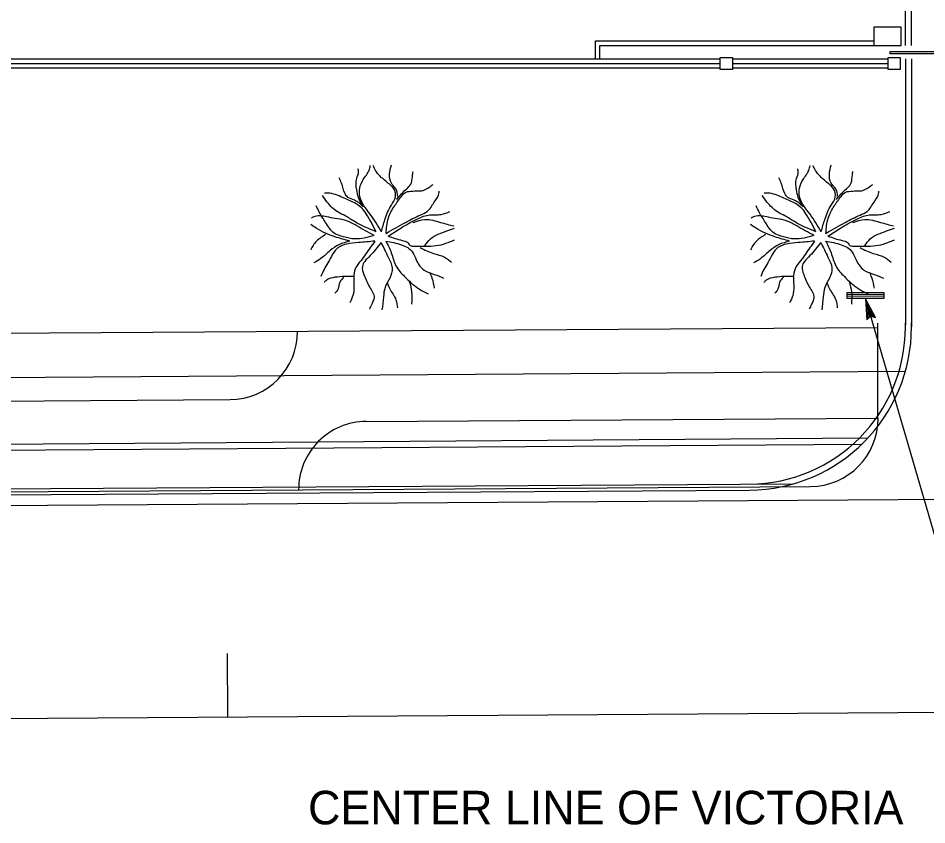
# Model space of a CAD drawing. Extents: x 6711323 to 6714641, y 1869258 to 1871224.
# Drawn here: x 6713028.7 to 6713129, y 1869579.7 to 1869668.7 of the extents above; entities that cross this region are included whole.
import ezdxf

# ---------------------------------------------------------------- set-up
doc = ezdxf.new("R2010")
doc.units = 0
for name, color, linetype in [('49 Planting', 7, 'Continuous'), ('Curb Gutter (21)', 7, 'Continuous'), ('Level 11', 7, 'Continuous'), ('Level 13', 7, 'Continuous'), ('Level 14', 7, 'Continuous'), ('Level 21', 7, 'Continuous'), ('Level 46', 7, 'Continuous'), ('Misc CnstDet(22)', 7, 'Continuous'), ('Profile Grid (9)', 7, 'Continuous'), ('Undefined (Lv26)', 7, 'Continuous')]:
    doc.layers.add(name, color=color, linetype=linetype)

msp = doc.modelspace()

# ---------------------------------------------------------------- linework, layer by layer
at = {"layer": '49 Planting'}
for p, q in [((6713124.24, 1869638.26), (6713120.2, 1869638.23)), ((6713124.25, 1869638.06), (6713120.2, 1869638.04)), ((6713122.22, 1869637.78), (6713130.69, 1869608.81)), ((6713122.22, 1869637.78), (6713122.22, 1869637.78)), ((6713122.37, 1869635.45), (6713122.37, 1869635.45)), ((6713123.35, 1869635.73), (6713123.35, 1869635.73))]:
    msp.add_line(p, q, dxfattribs=at)
for points in [[(6713120.22, 1869638.49), (6713124.25, 1869638.49), (6713124.25, 1869637.83), (6713120.22, 1869637.83)], [(6713123.35, 1869635.73), (6713122.22, 1869637.78), (6713122.37, 1869635.45), (6713122.48, 1869635.56), (6713122.37, 1869637.27), (6713123.2, 1869635.77), (6713123.05, 1869635.81), (6713122.51, 1869636.77), (6713122.59, 1869635.68), (6713122.69, 1869635.79), (6713122.66, 1869636.27), (6713122.89, 1869635.85), (6713122.78, 1869635.88), (6713122.37, 1869635.45), (6713122.78, 1869635.88)]]:
    msp.add_lwpolyline(points, close=True, dxfattribs=at)
at = {"layer": 'Curb Gutter (21)'}
for p, q in [((6713126.65, 1869665.74), (6713126.65, 1869718.07)), ((6713127.31, 1869665.74), (6713127.31, 1869718.07)), ((6713126.65, 1869664.24), (6713126.65, 1869634.91)), ((6713127.31, 1869664.24), (6713127.31, 1869634.67))]:
    msp.add_line(p, q, dxfattribs=at)
at = {"layer": 'Level 11'}
for p, q in [((6712930.92, 1869633.37), (6713123.56, 1869634.62)), ((6713001.11, 1869626.33), (6713052.11, 1869626.66)), ((6713067.13, 1869624.25), (6713123.56, 1869624.62)), ((6712940.02, 1869615.93), (6713116.17, 1869617.07)), ((6712948.69, 1869614.49), (6713181.17, 1869615.99))]:
    msp.add_line(p, q, dxfattribs=at)
for centre, start, end in [((6713052.06, 1869634.16), 270.3699, 0.3699), ((6713067.18, 1869616.75), 90.3699, 180.3699), ((6713116.12, 1869624.57), 270.3699, 0.3699)]:
    msp.add_arc(centre, 7.5, start, end, dxfattribs=at)
at = {"layer": 'Level 13'}
msp.add_line((6712709.06, 1869589.44), (6713820.2, 1869596.61), dxfattribs=at)
for centre, start, end in [((6713052.06, 1869634.16), 270.3699, 0.3699), ((6713067.18, 1869616.75), 90.3699, 180.3699)]:
    msp.add_arc(centre, 7.5, start, end, dxfattribs=at)
at = {"layer": 'Level 14'}
msp.add_lwpolyline([(6713051.79, 1869598.65), (6713051.83, 1869591.65)], dxfattribs=at)
at = {"layer": 'Level 21'}
for p, q in [((6713123.56, 1869635.1), (6713123.56, 1869624.62)), ((6712929.57, 1869633.37), (6713123.56, 1869634.62)), ((6713001.11, 1869626.33), (6713052.11, 1869626.66)), ((6713067.13, 1869624.25), (6713123.56, 1869624.62)), ((6712940.02, 1869615.93), (6713116.17, 1869617.07)), ((6712948.69, 1869614.49), (6713181.17, 1869615.99)), ((6712948.69, 1869614.49), (6713181.17, 1869615.99))]:
    msp.add_line(p, q, dxfattribs=at)
msp.add_arc((6713116.12, 1869624.57), 7.5, 270.3699, 0.3699, dxfattribs=at)
at = {"layer": 'Level 46'}
for p, q in [((6713126.65, 1869634.67), (6713126.65, 1869635.12)), ((6713127.31, 1869634.67), (6713127.31, 1869635.13)), ((6712931.76, 1869628.4), (6713126.64, 1869629.8)), ((6712936.07, 1869621.1), (6713122.51, 1869622.44)), ((6712936.75, 1869620.44), (6713121.86, 1869621.76)), ((6712944.24, 1869616.29), (6713114.28, 1869617.37)), ((6712949.09, 1869615.65), (6713109.43, 1869616.67))]:
    msp.add_line(p, q, dxfattribs=at)
for radius in [17.33, 18]:
    msp.add_arc((6713109.31, 1869634.67), radius, 270.3648, 0, dxfattribs=at)
at = {"layer": 'Misc CnstDet(22)'}
for p, q in [((6713123.15, 1869667.74), (6713123.15, 1869665.74)), ((6713126.15, 1869667.74), (6713123.15, 1869667.74)), ((6713126.15, 1869665.74), (6713126.15, 1869667.74)), ((6713092.42, 1869666.24), (6713123.17, 1869666.24)), ((6713092.42, 1869664.24), (6713092.42, 1869666.24)), ((6713092.92, 1869665.74), (6713126.14, 1869665.74)), ((6713092.92, 1869664.24), (6713092.92, 1869665.74)), ((6713123.15, 1869665.74), (6713126.15, 1869665.74)), ((6712985.7, 1869663.74), (6713106.2, 1869663.74)), ((6713107.54, 1869663.74), (6713124.67, 1869663.74))]:
    msp.add_line(p, q, dxfattribs=at)
msp.add_lwpolyline([(6713124.96, 1869665.07), (6713158.81, 1869665.07), (6713158.81, 1869664.82), (6713124.96, 1869664.82)], close=True, dxfattribs=at)
msp.add_lwpolyline([(6713124.96, 1869665.07), (6713158.81, 1869665.07), (6713158.81, 1869664.82), (6713124.96, 1869664.82)], close=True, dxfattribs=at)
at = {"layer": 'Profile Grid (9)'}
for points in [[(6713066.8, 1869647.94), (6713066.29, 1869648.96), (6713066.09, 1869649.8), (6713066.09, 1869651.05), (6713066.29, 1869651.77), (6713066.22, 1869652.13)], [(6713068.81, 1869645.18), (6713067.58, 1869647.1), (6713066.42, 1869649.08), (6713066.42, 1869649.98), (6713066.8, 1869650.93), (6713067.45, 1869651.95), (6713067.58, 1869652.49)], [(6713068.81, 1869645.18), (6713069.2, 1869646.5), (6713069.91, 1869648.12), (6713070.37, 1869649.02), (6713070.17, 1869649.92), (6713069.66, 1869650.45), (6713068.68, 1869651.29), (6713068.16, 1869651.95), (6713067.91, 1869652.49)], [(6713070.63, 1869649.08), (6713070.43, 1869649.86), (6713070.3, 1869650.04), (6713069.91, 1869650.52), (6713069.72, 1869651.53), (6713069.91, 1869652.55)], [(6713115.34, 1869647.94), (6713114.82, 1869648.96), (6713114.62, 1869649.8), (6713114.62, 1869651.05), (6713114.82, 1869651.77), (6713114.75, 1869652.13)], [(6713117.35, 1869645.18), (6713116.11, 1869647.1), (6713114.95, 1869649.08), (6713114.95, 1869649.98), (6713115.34, 1869650.93), (6713115.98, 1869651.95), (6713116.11, 1869652.49)], [(6713117.35, 1869645.18), (6713117.73, 1869646.5), (6713118.45, 1869648.12), (6713118.9, 1869649.02), (6713118.71, 1869649.92), (6713118.19, 1869650.45), (6713117.22, 1869651.29), (6713116.7, 1869651.95), (6713116.44, 1869652.49)], [(6713119.16, 1869649.08), (6713118.97, 1869649.86), (6713118.84, 1869650.04), (6713118.45, 1869650.52), (6713118.25, 1869651.53), (6713118.45, 1869652.55)], [(6713066.8, 1869647.94), (6713065.83, 1869648.66), (6713065.12, 1869648.96), (6713064.8, 1869649.38), (6713064.41, 1869650.52), (6713064.15, 1869651.11)], [(6713070.5, 1869648.72), (6713071.21, 1869649.56), (6713072.12, 1869650.57), (6713072.25, 1869651.47), (6713072.31, 1869651.83)], [(6713115.34, 1869647.94), (6713114.36, 1869648.66), (6713113.65, 1869648.96), (6713113.33, 1869649.38), (6713112.94, 1869650.52), (6713112.68, 1869651.11)], [(6713119.03, 1869648.72), (6713119.74, 1869649.56), (6713120.65, 1869650.57), (6713120.78, 1869651.47), (6713120.84, 1869651.83)], [(6713069.33, 1869645), (6713069.59, 1869646.68), (6713070.24, 1869648), (6713071.02, 1869649.08), (6713071.53, 1869649.56), (6713071.86, 1869649.62), (6713072.7, 1869649.68), (6713073.41, 1869649.74), (6713074.26, 1869650.22), (6713074.51, 1869650.4)], [(6713117.86, 1869645), (6713118.12, 1869646.68), (6713118.77, 1869648), (6713119.55, 1869649.08), (6713120.07, 1869649.56), (6713120.39, 1869649.62), (6713121.23, 1869649.68), (6713121.95, 1869649.74), (6713122.79, 1869650.22), (6713123.05, 1869650.4)], [(6713068.23, 1869645.18), (6713065.85, 1869646.29), (6713064.81, 1869646.93), (6713064.03, 1869647.33), (6713062.83, 1869648.45), (6713062.31, 1869649.17)], [(6713068.23, 1869645.18), (6713067.13, 1869647.16), (6713066.61, 1869647.82), (6713065.83, 1869648.36), (6713064.54, 1869648.96), (6713062.92, 1869649.44), (6713062.53, 1869649.44)], [(6713069.33, 1869645), (6713071.46, 1869646.21), (6713073.09, 1869647.01), (6713073.87, 1869647.41), (6713074.65, 1869648.45), (6713075.17, 1869649.49), (6713075.17, 1869649.65)], [(6713116.76, 1869645.18), (6713114.38, 1869646.29), (6713113.34, 1869646.93), (6713112.57, 1869647.33), (6713111.36, 1869648.45), (6713110.84, 1869649.17)], [(6713116.76, 1869645.18), (6713115.66, 1869647.16), (6713115.14, 1869647.82), (6713114.36, 1869648.36), (6713113.07, 1869648.96), (6713111.45, 1869649.44), (6713111.06, 1869649.44)], [(6713117.86, 1869645), (6713119.99, 1869646.21), (6713121.63, 1869647.01), (6713122.4, 1869647.41), (6713123.18, 1869648.45), (6713123.7, 1869649.49), (6713123.7, 1869649.65)], [(6713068, 1869644.78), (6713065.85, 1869644.38), (6713064.64, 1869644.62), (6713063.6, 1869645.02), (6713062.65, 1869646.21), (6713061.96, 1869647.33), (6713061.62, 1869648.05)], [(6713069.56, 1869644.7), (6713070.94, 1869645.58), (6713072.66, 1869646.53), (6713073.96, 1869647.01), (6713075.42, 1869647.09), (6713076.37, 1869647.41)], [(6713116.54, 1869644.78), (6713114.38, 1869644.38), (6713113.17, 1869644.62), (6713112.14, 1869645.02), (6713111.19, 1869646.21), (6713110.5, 1869647.33), (6713110.15, 1869648.05)], [(6713118.09, 1869644.7), (6713119.47, 1869645.58), (6713121.2, 1869646.53), (6713122.49, 1869647.01), (6713123.96, 1869647.09), (6713124.91, 1869647.41)], [(6713068, 1869644.78), (6713066.11, 1869645.81), (6713064.98, 1869646.37), (6713063.95, 1869646.61), (6713063, 1869646.77), (6713061.45, 1869646.85), (6713061.1, 1869646.69)], [(6713072.32, 1869646.21), (6713073.61, 1869646.53), (6713075.34, 1869646.21), (6713076.8, 1869645.81)], [(6713116.54, 1869644.78), (6713114.64, 1869645.81), (6713113.52, 1869646.37), (6713112.48, 1869646.61), (6713111.53, 1869646.77), (6713109.98, 1869646.85), (6713109.63, 1869646.69)], [(6713120.85, 1869646.21), (6713122.15, 1869646.53), (6713123.87, 1869646.21), (6713125.34, 1869645.81)], [(6713065.33, 1869644.14), (6713063.69, 1869644.62), (6713062.65, 1869645.02), (6713061.62, 1869645.58), (6713061.01, 1869645.97)], [(6713073.61, 1869643.66), (6713074.22, 1869644.38), (6713076.03, 1869645.26), (6713076.89, 1869645.58)], [(6713113.86, 1869644.14), (6713112.22, 1869644.62), (6713111.19, 1869645.02), (6713110.15, 1869645.58), (6713109.55, 1869645.97)], [(6713122.15, 1869643.66), (6713122.75, 1869644.38), (6713124.56, 1869645.26), (6713125.42, 1869645.58)], [(6713062.65, 1869644.86), (6713062.14, 1869644.54), (6713061.27, 1869643.66), (6713061.01, 1869643.18)], [(6713065.33, 1869644.14), (6713064.12, 1869643.74), (6713063.17, 1869643.1), (6713062.14, 1869642.22), (6713061.36, 1869641.74)], [(6713068.09, 1869644.14), (6713066.28, 1869643.98), (6713064.98, 1869643.82), (6713064.03, 1869643.42), (6713063.43, 1869642.7), (6713062.91, 1869641.74), (6713062.48, 1869641.02), (6713062.14, 1869640.23)], [(6713068.09, 1869644.14), (6713067.57, 1869643.42), (6713066.54, 1869641.98), (6713065.93, 1869641.1), (6713065.76, 1869640.07), (6713065.67, 1869638.15), (6713065.33, 1869637.35)], [(6713069.3, 1869644.14), (6713069.9, 1869642.86), (6713070.42, 1869641.42), (6713071.37, 1869640.23), (6713072.84, 1869638.95), (6713073.96, 1869638.31)], [(6713069.3, 1869644.14), (6713071.02, 1869643.74), (6713071.71, 1869643.42), (6713072.23, 1869642.94), (6713072.66, 1869642.06), (6713073.53, 1869640.94), (6713074.65, 1869640.47), (6713075.68, 1869640.07)], [(6713069.56, 1869644.7), (6713071.11, 1869644.22), (6713071.71, 1869643.98), (6713071.97, 1869643.66), (6713072.49, 1869643.58), (6713073.7, 1869643.58), (6713075.94, 1869643.9), (6713076.89, 1869644.3)], [(6713111.19, 1869644.86), (6713110.67, 1869644.54), (6713109.81, 1869643.66), (6713109.55, 1869643.18)], [(6713113.86, 1869644.14), (6713112.65, 1869643.74), (6713111.7, 1869643.1), (6713110.67, 1869642.22), (6713109.89, 1869641.74)], [(6713116.62, 1869644.14), (6713114.81, 1869643.98), (6713113.52, 1869643.82), (6713112.57, 1869643.42), (6713111.96, 1869642.7), (6713111.45, 1869641.74), (6713111.01, 1869641.02), (6713110.67, 1869640.23)], [(6713116.62, 1869644.14), (6713116.1, 1869643.42), (6713115.07, 1869641.98), (6713114.47, 1869641.1), (6713114.29, 1869640.07), (6713114.21, 1869638.15), (6713113.86, 1869637.35)], [(6713117.83, 1869644.14), (6713118.43, 1869642.86), (6713118.95, 1869641.42), (6713119.9, 1869640.23), (6713121.37, 1869638.95), (6713122.49, 1869638.31)], [(6713117.83, 1869644.14), (6713119.56, 1869643.74), (6713120.25, 1869643.42), (6713120.76, 1869642.94), (6713121.2, 1869642.06), (6713122.06, 1869640.94), (6713123.18, 1869640.47), (6713124.22, 1869640.07)], [(6713118.09, 1869644.7), (6713119.64, 1869644.22), (6713120.25, 1869643.98), (6713120.51, 1869643.66), (6713121.02, 1869643.58), (6713122.23, 1869643.58), (6713124.47, 1869643.9), (6713125.42, 1869644.3)], [(6713068.78, 1869643.98), (6713067.57, 1869642.54), (6713066.97, 1869641.9), (6713066.71, 1869641.34), (6713066.88, 1869640.47), (6713067.49, 1869639.11), (6713068, 1869637.91), (6713067.74, 1869637.19), (6713067.49, 1869636.63)], [(6713068.78, 1869643.98), (6713069.56, 1869642.38), (6713069.99, 1869641.18), (6713069.73, 1869640.07), (6713069.21, 1869639.03), (6713069.04, 1869637.99), (6713068.87, 1869636.55)], [(6713073.09, 1869643.42), (6713074.56, 1869642.78), (6713075.77, 1869642.38), (6713076.55, 1869641.82)], [(6713117.31, 1869643.98), (6713116.1, 1869642.54), (6713115.5, 1869641.9), (6713115.24, 1869641.34), (6713115.41, 1869640.47), (6713116.02, 1869639.11), (6713116.54, 1869637.91), (6713116.28, 1869637.19), (6713116.02, 1869636.63)], [(6713117.31, 1869643.98), (6713118.09, 1869642.38), (6713118.52, 1869641.18), (6713118.26, 1869640.07), (6713117.74, 1869639.03), (6713117.57, 1869637.99), (6713117.4, 1869636.55)], [(6713121.63, 1869643.42), (6713123.09, 1869642.78), (6713124.3, 1869642.38), (6713125.08, 1869641.82)], [(6713065.76, 1869640.23), (6713063.69, 1869640.15), (6713062.74, 1869639.83), (6713062.48, 1869639.59)], [(6713064.64, 1869640.15), (6713064.21, 1869639.59), (6713064.03, 1869638.87), (6713063.69, 1869638.39)], [(6713074.13, 1869640.7), (6713074.39, 1869640.07), (6713074.65, 1869638.95)], [(6713114.29, 1869640.23), (6713112.22, 1869640.15), (6713111.27, 1869639.83), (6713111.01, 1869639.59)], [(6713113.17, 1869640.15), (6713112.74, 1869639.59), (6713112.57, 1869638.87), (6713112.22, 1869638.39)], [(6713122.66, 1869640.7), (6713122.92, 1869640.07), (6713123.18, 1869638.95)], [(6713069.47, 1869639.51), (6713069.73, 1869638.87), (6713070.42, 1869637.67), (6713070.59, 1869636.79)], [(6713071.89, 1869639.67), (6713072.15, 1869638.55), (6713072.15, 1869637.19)], [(6713118, 1869639.51), (6713118.26, 1869638.87), (6713118.95, 1869637.67), (6713119.12, 1869636.79)], [(6713120.42, 1869639.67), (6713120.68, 1869638.55), (6713120.68, 1869637.19)]]:
    msp.add_spline(points, degree=3, dxfattribs=at)
at = {"layer": 'Undefined (Lv26)'}
for p, q in [((6712985.7, 1869664.24), (6713106.2, 1869664.24)), ((6713106.2, 1869663.06), (6713106.2, 1869664.39)), ((6713106.2, 1869664.39), (6713107.54, 1869664.39)), ((6713107.54, 1869664.39), (6713107.54, 1869663.06)), ((6713107.54, 1869664.24), (6713124.73, 1869664.24)), ((6713124.73, 1869663.06), (6713124.73, 1869664.39)), ((6713124.73, 1869664.39), (6713126.06, 1869664.39)), ((6713126.06, 1869664.39), (6713126.06, 1869663.06)), ((6712985.7, 1869663.24), (6713106.2, 1869663.24)), ((6713107.54, 1869663.24), (6713124.67, 1869663.24)), ((6713107.54, 1869663.06), (6713106.2, 1869663.06)), ((6713126.06, 1869663.06), (6713124.73, 1869663.06))]:
    msp.add_line(p, q, dxfattribs=at)

# ---------------------------------------------------------------- texts
at = {"layer": 'Level 14'}
msp.add_text('CENTER LINE OF VICTORIA', height=3.7, dxfattribs=at).set_placement((6713060.72, 1869579.8))

doc.saveas('drawing.dxf')
